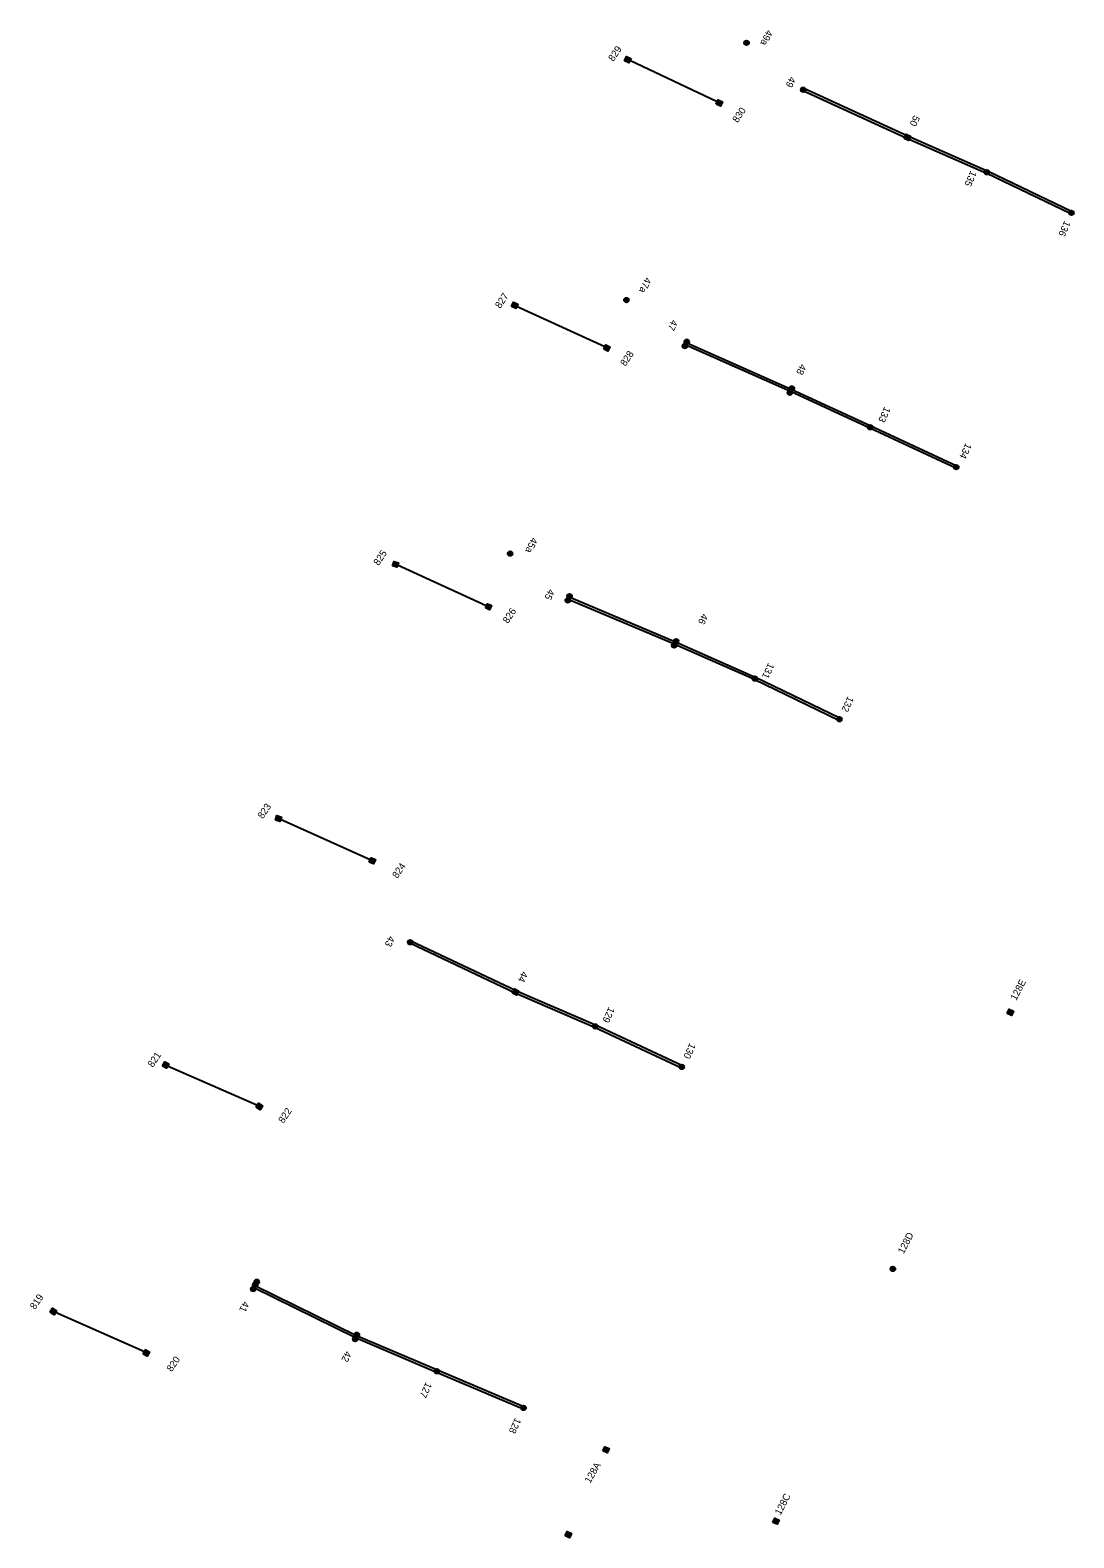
# Model space of a CAD drawing. Extents: x -595867 to -593796, y -1159595 to -1157495.
# Drawn here: x -595151.5 to -594928.1, y -1158898 to -1158575.2 of the extents above; entities that cross this region are included whole.
import ezdxf

# ---------------------------------------------------------------- set-up
doc = ezdxf.new("R2010")
doc.units = 0
for name, color, linetype in [('BVK_kanalizace_jednotna_nova', 7, 'Continuous'), ('DKM18', 7, 'Continuous'), ('DKM19', 7, 'Continuous'), ('SO31_06_54_1-protlak', 7, 'Continuous'), ('Vrstva 2', 7, 'Continuous')]:
    doc.layers.add(name, color=color, linetype=linetype)

# ---------------------------------------------------------------- blocks, each defined once
blk = doc.blocks.new('C661_2')
at = {"layer": 'SO31_06_54_1-protlak'}
for p, q in [((-0.005, 0.0003), (-0.0003, 0.005)), ((-0.005, -0.005), (0.005, 0.005)), ((0.0003, -0.005), (0.005, -0.0003))]:
    blk.add_line(p, q, dxfattribs=at)
blk.add_lwpolyline([(-0.005, 0.005), (0.005, 0.005), (0.005, -0.005), (-0.005, -0.005)], close=True, dxfattribs=at)
blk.add_lwpolyline([(-0.005, 0.005), (0.005, 0.005), (0.005, -0.005), (-0.005, -0.005), (-0.005, 0.005)], dxfattribs=at)

msp = doc.modelspace()

# ---------------------------------------------------------------- linework, layer by layer
at = {"layer": 'BVK_kanalizace_jednotna_nova'}
for p, q in [((-594998.27, -1158578.41), (-594998.43, -1158577.51)), ((-594997.9, -1158578.35), (-594998.06, -1158577.44)), ((-595023.86, -1158581.94), (-595024.09, -1158581.32)), ((-595023.38, -1158582.17), (-595023.87, -1158580.84)), ((-595023.16, -1158581.69), (-595023.39, -1158581.06)), ((-594986.13, -1158588.44), (-594986.29, -1158587.54)), ((-594985.76, -1158588.39), (-594985.92, -1158587.47)), ((-595004.25, -1158591.23), (-595004.47, -1158590.61)), ((-595003.77, -1158591.45), (-595004.25, -1158590.13)), ((-595003.54, -1158590.98), (-595003.77, -1158590.35)), ((-594946.39, -1158605.99), (-594947.24, -1158605.65)), ((-594946.24, -1158605.65), (-594947.1, -1158605.3)), ((-594928.27, -1158614.67), (-594929.12, -1158614.33)), ((-594928.12, -1158614.33), (-594928.98, -1158613.98)), ((-595048.03, -1158634.58), (-595048.26, -1158633.96)), ((-595047.55, -1158634.8), (-595048.04, -1158633.48)), ((-595047.33, -1158634.32), (-595047.56, -1158633.69)), ((-595023.97, -1158633.47), (-595024.13, -1158632.57)), ((-595023.6, -1158633.41), (-595023.77, -1158632.5)), ((-595011.06, -1158642.42), (-595011.22, -1158641.52)), ((-595010.69, -1158642.36), (-595010.85, -1158641.45)), ((-595028.3, -1158643.69), (-595028.53, -1158643.07)), ((-595027.82, -1158643.91), (-595028.31, -1158642.59)), ((-595027.6, -1158643.44), (-595027.83, -1158642.81)), ((-595011.46, -1158643.34), (-595011.62, -1158642.44)), ((-595011.09, -1158643.28), (-595011.26, -1158642.37)), ((-594989, -1158653.31), (-594989.16, -1158652.41)), ((-594988.63, -1158653.26), (-594988.8, -1158652.34)), ((-594988.57, -1158652.39), (-594988.73, -1158651.49)), ((-594988.2, -1158652.33), (-594988.36, -1158651.42)), ((-594971.8, -1158660.7), (-594971.96, -1158659.8)), ((-594971.43, -1158660.64), (-594971.59, -1158659.73)), ((-594953.38, -1158669.26), (-594953.54, -1158668.36)), ((-594953.01, -1158669.21), (-594953.17, -1158668.29)), ((-595048.5, -1158687.72), (-595048.66, -1158686.81)), ((-595073.5, -1158690.04), (-595073.79, -1158689.45)), ((-595073, -1158690.22), (-595073.61, -1158688.95)), ((-595072.82, -1158689.72), (-595073.11, -1158689.12)), ((-595048.87, -1158687.78), (-595049.03, -1158686.88)), ((-595036.15, -1158696.88), (-595036.31, -1158695.98)), ((-595035.78, -1158696.82), (-595035.95, -1158695.91)), ((-595053.63, -1158699.11), (-595053.86, -1158698.49)), ((-595053.15, -1158699.33), (-595053.64, -1158698.01)), ((-595052.93, -1158698.85), (-595053.16, -1158698.23)), ((-595036.55, -1158697.79), (-595036.71, -1158696.89)), ((-595036.18, -1158697.74), (-595036.34, -1158696.82)), ((-595013.34, -1158706.53), (-595013.5, -1158705.63)), ((-595012.97, -1158706.48), (-595013.14, -1158705.56)), ((-595013.76, -1158707.44), (-595013.92, -1158706.54)), ((-595013.39, -1158707.39), (-595013.56, -1158706.47)), ((-594996.5, -1158714.52), (-594996.66, -1158713.62)), ((-594996.13, -1158714.47), (-594996.29, -1158713.55)), ((-594978.02, -1158723.19), (-594978.18, -1158722.28)), ((-594978.39, -1158723.25), (-594978.55, -1158722.35)), ((-595098.56, -1158744.5), (-595098.84, -1158743.9)), ((-595098.06, -1158744.68), (-595098.66, -1158743.4)), ((-595097.88, -1158744.18), (-595098.16, -1158743.57)), ((-595078.49, -1158753.51), (-595078.73, -1158752.9)), ((-595078, -1158753.72), (-595078.53, -1158752.41)), ((-595077.79, -1158753.23), (-595078.04, -1158752.61)), ((-595070.24, -1158770.98), (-595070.4, -1158770.08)), ((-595069.87, -1158770.93), (-595070.03, -1158770.01)), ((-595030.7, -1158788.99), (-595030.86, -1158788.09)), ((-595030.33, -1158788.94), (-595030.49, -1158788.02)), ((-595122.74, -1158797.19), (-595122.9, -1158796.54)), ((-595122.28, -1158797.46), (-595122.63, -1158796.09)), ((-595122.01, -1158797), (-595122.18, -1158796.36)), ((-595012.12, -1158797.69), (-595012.28, -1158796.79)), ((-595011.75, -1158797.63), (-595011.92, -1158796.72)), ((-595102.71, -1158806.09), (-595102.87, -1158805.45)), ((-595102.25, -1158806.36), (-595102.6, -1158805)), ((-595101.98, -1158805.91), (-595102.15, -1158805.26)), ((-594966.49, -1158840.8), (-594967.34, -1158840.46)), ((-594966.34, -1158840.46), (-594967.2, -1158840.11)), ((-595103.85, -1158845.24), (-595104.01, -1158844.34)), ((-595103.48, -1158845.19), (-595103.65, -1158844.27)), ((-595103.42, -1158844.34), (-595103.58, -1158843.44)), ((-595103.08, -1158843.69), (-595103.24, -1158842.79)), ((-595103.05, -1158844.28), (-595103.22, -1158843.37)), ((-595102.71, -1158843.63), (-595102.88, -1158842.72)), ((-595146.82, -1158849.98), (-595146.98, -1158849.34)), ((-595146.36, -1158850.25), (-595146.71, -1158848.88)), ((-595146.09, -1158849.8), (-595146.26, -1158849.15)), ((-595081.66, -1158855.01), (-595081.82, -1158854.11)), ((-595081.29, -1158854.96), (-595081.45, -1158854.04)), ((-595126.44, -1158859.13), (-595126.79, -1158857.77)), ((-595082.03, -1158855.95), (-595082.19, -1158855.05)), ((-595081.66, -1158855.89), (-595081.83, -1158854.98)), ((-595126.9, -1158858.86), (-595127.06, -1158858.22)), ((-595126.17, -1158858.68), (-595126.33, -1158858.03)), ((-595064.53, -1158862.85), (-595064.69, -1158861.95)), ((-595064.16, -1158862.79), (-595064.32, -1158861.88)), ((-595046, -1158870.7), (-595046.16, -1158869.8)), ((-595045.63, -1158870.65), (-595045.79, -1158869.73))]:
    msp.add_line(p, q, dxfattribs=at)
for points in [[(-595024.29, -1158581.75), (-595023.86, -1158580.84), (-595022.96, -1158581.26), (-595023.38, -1158582.17)], [(-595004.67, -1158591.03), (-595004.25, -1158590.13), (-595003.34, -1158590.55), (-595003.76, -1158591.46)], [(-595048.46, -1158634.38), (-595048.03, -1158633.47), (-595047.13, -1158633.89), (-595047.55, -1158634.8)], [(-595028.73, -1158643.49), (-595028.3, -1158642.58), (-595027.4, -1158643.01), (-595027.82, -1158643.91)], [(-595073.94, -1158689.89), (-595073.61, -1158688.95), (-595072.67, -1158689.28), (-595073, -1158690.22)], [(-595054.06, -1158698.91), (-595053.63, -1158698.01), (-595052.73, -1158698.43), (-595053.15, -1158699.33)], [(-595099, -1158744.34), (-595098.66, -1158743.4), (-595097.72, -1158743.73), (-595098.05, -1158744.68)], [(-595078.92, -1158753.33), (-595078.53, -1158752.41), (-595077.6, -1158752.8), (-595078, -1158753.72)], [(-595123.14, -1158796.95), (-595122.63, -1158796.09), (-595121.77, -1158796.6), (-595122.28, -1158797.46)], [(-595103.11, -1158805.85), (-595102.6, -1158804.99), (-595101.74, -1158805.5), (-595102.25, -1158806.36)], [(-595147.22, -1158849.74), (-595146.71, -1158848.88), (-595145.85, -1158849.39), (-595146.36, -1158850.25)], [(-595127.3, -1158858.62), (-595126.79, -1158857.77), (-595125.93, -1158858.28), (-595126.44, -1158859.14)]]:
    msp.add_lwpolyline(points, close=True, dxfattribs=at)
for points in [[(-595024.29, -1158581.75), (-595023.86, -1158580.84), (-595022.96, -1158581.26), (-595023.38, -1158582.17), (-595024.29, -1158581.75)], [(-595004.47, -1158590.59), (-595023.17, -1158581.73)], [(-594963.84, -1158598.4), (-594986.12, -1158588.19)], [(-594963.63, -1158597.94), (-594985.92, -1158587.73)], [(-595004.67, -1158591.03), (-595004.25, -1158590.13), (-595003.34, -1158590.55), (-595003.76, -1158591.46), (-595004.67, -1158591.03)], [(-594946.84, -1158605.87), (-594963.84, -1158598.4)], [(-594946.64, -1158605.41), (-594963.64, -1158597.94)], [(-594928.73, -1158614.54), (-594946.85, -1158605.86)], [(-594928.51, -1158614.09), (-594946.63, -1158605.41)], [(-595048.46, -1158634.38), (-595048.03, -1158633.47), (-595047.13, -1158633.89), (-595047.55, -1158634.8), (-595048.46, -1158634.38)], [(-595028.51, -1158643), (-595047.42, -1158634.39)], [(-595028.73, -1158643.49), (-595028.3, -1158642.58), (-595027.4, -1158643.01), (-595027.82, -1158643.91), (-595028.73, -1158643.49)], [(-594988.79, -1158652.6), (-595011.27, -1158642.62)], [(-594988.58, -1158652.14), (-595011.07, -1158642.16)], [(-594971.79, -1158660.45), (-594988.79, -1158652.6)], [(-594971.58, -1158659.99), (-594988.58, -1158652.14)], [(-594953.38, -1158669.01), (-594971.8, -1158660.45)], [(-594953.17, -1158668.55), (-594971.58, -1158659.99)], [(-595073.94, -1158689.89), (-595073.61, -1158688.95), (-595072.67, -1158689.28), (-595073, -1158690.22), (-595073.94, -1158689.89)], [(-595053.86, -1158698.44), (-595072.84, -1158689.73)], [(-595054.06, -1158698.91), (-595053.63, -1158698.01), (-595052.73, -1158698.43), (-595053.15, -1158699.33), (-595054.06, -1158698.91)], [(-595013.47, -1158706.75), (-595036.34, -1158697.08)], [(-595013.34, -1158706.28), (-595036.14, -1158696.62)], [(-594996.49, -1158714.27), (-595013.54, -1158706.74)], [(-594996.29, -1158713.81), (-595013.34, -1158706.28)], [(-594978.39, -1158722.99), (-594996.5, -1158714.27)], [(-594978.18, -1158722.54), (-594996.28, -1158713.81)], [(-595099, -1158744.34), (-595098.66, -1158743.4), (-595097.72, -1158743.73), (-595098.05, -1158744.68), (-595099, -1158744.34)], [(-595078.72, -1158752.85), (-595097.91, -1158744.24)], [(-595078.92, -1158753.33), (-595078.53, -1158752.41), (-595077.6, -1158752.8), (-595078, -1158753.72), (-595078.92, -1158753.33)], [(-595047.71, -1158781.39), (-595070.24, -1158770.73)], [(-595047.5, -1158780.94), (-595070.02, -1158770.27)], [(-595030.69, -1158788.74), (-595047.71, -1158781.39)], [(-595030.49, -1158788.28), (-595047.51, -1158780.93)], [(-595012.11, -1158797.44), (-595030.7, -1158788.74)], [(-595011.9, -1158796.99), (-595030.48, -1158788.28)], [(-595123.14, -1158796.95), (-595122.63, -1158796.09), (-595121.77, -1158796.6), (-595122.28, -1158797.46), (-595123.14, -1158796.95)], [(-595102.83, -1158805.44), (-595122.05, -1158797.02)], [(-595103.11, -1158805.85), (-595102.6, -1158804.99), (-595101.74, -1158805.5), (-595102.25, -1158806.36), (-595103.11, -1158805.85)], [(-595081.86, -1158855.22), (-595103.64, -1158844.53)], [(-595081.64, -1158854.77), (-595103.42, -1158844.08)], [(-595147.22, -1158849.74), (-595146.71, -1158848.88), (-595145.85, -1158849.39), (-595146.36, -1158850.25), (-595147.22, -1158849.74)], [(-595127.01, -1158858.23), (-595146.06, -1158849.78)], [(-595127.3, -1158858.62), (-595126.79, -1158857.77), (-595125.93, -1158858.28), (-595126.44, -1158859.14), (-595127.3, -1158858.62)], [(-595064.52, -1158862.6), (-595081.85, -1158855.23)], [(-595064.32, -1158862.14), (-595081.65, -1158854.77)], [(-595045.99, -1158870.45), (-595064.52, -1158862.6)], [(-595045.8, -1158869.99), (-595064.32, -1158862.14)]]:
    msp.add_lwpolyline(points, dxfattribs=at)
for centre in [(-594998.16, -1158577.92), (-594998.16, -1158577.92), (-594986.02, -1158587.96), (-594986.02, -1158587.96), (-594946.74, -1158605.64), (-594946.74, -1158605.64), (-594928.62, -1158614.32), (-594928.62, -1158614.32), (-595023.86, -1158632.99), (-595023.86, -1158632.99), (-595010.95, -1158641.94), (-595010.95, -1158641.94), (-595011.35, -1158642.86), (-595011.35, -1158642.86), (-594988.89, -1158652.83), (-594988.89, -1158652.83), (-594988.46, -1158651.91), (-594988.46, -1158651.91), (-594971.69, -1158660.22), (-594971.69, -1158660.22), (-594953.27, -1158668.78), (-594953.27, -1158668.78), (-595048.76, -1158687.3), (-595048.76, -1158687.3), (-595036.04, -1158696.4), (-595036.04, -1158696.4), (-595036.44, -1158697.31), (-595036.44, -1158697.31), (-595013.23, -1158706.05), (-595013.23, -1158706.05), (-595013.65, -1158706.96), (-595013.65, -1158706.96), (-594996.39, -1158714.04), (-594996.39, -1158714.04), (-594978.28, -1158722.77), (-594978.28, -1158722.77), (-595070.13, -1158770.5), (-595070.13, -1158770.5), (-595030.59, -1158788.51), (-595030.59, -1158788.51), (-595012.01, -1158797.21), (-595012.01, -1158797.21), (-594966.84, -1158840.45), (-594966.84, -1158840.45), (-595103.74, -1158844.76), (-595103.74, -1158844.76), (-595103.31, -1158843.85), (-595103.31, -1158843.85), (-595102.97, -1158843.21), (-595102.97, -1158843.21), (-595081.55, -1158854.53), (-595081.55, -1158854.53), (-595081.92, -1158855.46), (-595081.92, -1158855.46), (-595064.42, -1158862.37), (-595064.42, -1158862.37), (-595045.89, -1158870.22), (-595045.89, -1158870.22)]:
    msp.add_circle(centre, 0.5, dxfattribs=at)

# ---------------------------------------------------------------- block references
at = {"layer": 'BVK_kanalizace_jednotna_nova', "xscale": 99.99959234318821, "yscale": 99.99959234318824, "rotation": 65.45078500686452}
for p in [(-594963.74, -1158598.17), (-595047.61, -1158781.16)]:
    msp.add_blockref('C661_2', p, dxfattribs=at)
at = {"layer": 'Vrstva 2', "xscale": 99.99959234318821, "yscale": 99.99959234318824, "rotation": 65.45078500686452}
for p in [(-594941.72, -1158785.51), (-595028.23, -1158879.18), (-594991.87, -1158894.47), (-595036.32, -1158897.37)]:
    msp.add_blockref('C661_2', p, dxfattribs=at)

# ---------------------------------------------------------------- texts
at = {"layer": 'BVK_kanalizace_jednotna_nova'}
for s, p in [('829', (-595026.65, -1158582.01)), ('830', (-595000.08, -1158595.16)), ('827', (-595050.87, -1158634.91)), ('828', (-595024.08, -1158647.28)), ('825', (-595076.9, -1158689.96)), ('826', (-595049.23, -1158702.37)), ('823', (-595101.68, -1158744.2)), ('824', (-595072.89, -1158756.94)), ('821', (-595125.22, -1158797.41)), ('822', (-595097.26, -1158809.39)), ('819', (-595150.41, -1158849.26)), ('820', (-595121.17, -1158862.59))]:
    msp.add_text(s, height=1.5, rotation=56, dxfattribs=at).set_placement(p)
at = {"layer": 'DKM18'}
for s, p in [('128E', (-594940.45, -1158783.1)), ('128D', (-594964.55, -1158837.36)), ('128C', (-594990.89, -1158893.29))]:
    msp.add_text(s, height=1.5, rotation=62.6209, dxfattribs=at).set_placement(p)
at = {"layer": 'DKM19'}
for s, rotation, p in [('49a', 245.2949, (-594993.84, -1158575.02)), ('49', 245.319, (-594988.91, -1158585.03)), ('50', 245.346, (-594962.37, -1158593.33)), ('135', 245.319, (-594950.18, -1158605.2)), ('136', 245.319, (-594930.08, -1158615.9)), ('47a', 245.3613, (-595019.82, -1158628.01)), ('47', 245.3037, (-595014.16, -1158637.09)), ('48', 245.3891, (-594986.64, -1158646.56)), ('133', 245.3782, (-594968.63, -1158655.73)), ('134', 245.3427, (-594951.25, -1158663.52)), ('45a', 245.3529, (-595044.15, -1158683.7)), ('45', 245.3037, (-595040.52, -1158694.74)), ('46', 245.3891, (-595007.67, -1158700)), ('131', 245.3891, (-594993.5, -1158710.58)), ('132', 245.3891, (-594976.48, -1158717.72)), ('43', 245.4443, (-595074.71, -1158769.01)), ('44', 245.3727, (-595046.22, -1158776.6)), ('129', 245.4443, (-595027.65, -1158784.26)), ('130', 245.4443, (-595010.32, -1158791.98)), ('41', 245.3813, (-595105.85, -1158847.24)), ('42', 245.4593, (-595083.99, -1158857.91)), ('127', 245.024, (-595066.76, -1158864.58)), ('128', 245.024, (-595047.67, -1158872.23)), ('128A', 60, (-595031.63, -1158886.47))]:
    msp.add_text(s, height=1.5, rotation=rotation, dxfattribs=at).set_placement(p)

doc.saveas('drawing.dxf')
